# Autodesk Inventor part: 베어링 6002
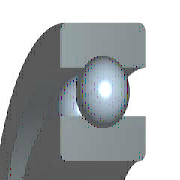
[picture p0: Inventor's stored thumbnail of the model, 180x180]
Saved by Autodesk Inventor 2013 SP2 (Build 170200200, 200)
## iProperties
IsCustomPart: 0
Created: 2012-02
Part Number: 베어링 6002
Material: 강철, 연강
Description: 깊은 그루브 볼 베어링
Document SubType Name: Modeling
Standard: KS B 2023
Designer: mduedu
Standards Organization: KS
Language: ko-KR
Size Designation: 6002 - 15 x 32 x 9
Categories: <MemberInstance><Categories><Category DisplayName="샤프트 부품" InternalName="7f7aeb1f-a693-4053-b835-cee3144e0d98" Mnemonic="SHFT"><Category DisplayName="베어링" Inter
Density: 1 g/cm^3
Author: mduedu
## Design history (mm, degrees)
sketch "스케치" dims "d0" = 4.42 (= -0.26 x WD + 0.26 x BD)
  geometry: L1 (2.29, 11.75)-(6.71, 11.75); L2 (4.5, 11.75)-(4.5, 9.54); L3 (4.5, 11.75)-(4.5, 13.96); L4 (2.858, 10.271)-(0, 10.271); L5 (0, 7.5)-(9, 7.5); L6 (2.858, 13.229)-(0, 13.229); L7 (0, 16)-(9, 16); L8 (9, 7.5)-(9, 10.271); L9 (6.142, 10.271)-(9, 10.271); L10 (6.142, 13.229)-(9, 13.229); L11 (9, 16)-(9, 13.229); L12 (-1.4, 0)-(8.4, 0) reference; L13 (0, -0.3)-(0, 5.3) reference
  constraints: 22 end point, 4 point on line, 2 collinear, 2 perpendicular, 2 symmetric about line, 1 midpoint, 1 parallel, 14 other
  dimensions: "d9" = 15 diameter of L5 L12 (= WD); "d11" = 32 diameter of L7 L12 (= BD); "d12" = 9 distance between parallel lines of L8 L13 (= KB); "d13" = 20.542 diameter of L9 L12 (= 0.326 x BD + 0.674 x WD)
revolve "본체" stored, may be unused: angle "d6" = 90 deg
revolve "볼" stored, may be unused: angle "d7" = 90 deg
pattern_circular "IDS_ARRAYBALL[SIMPL:T]" dims angle "d3" = 360 deg
body "Solid1"
fillet "모깎기1" dims "d1" = 0.3 (= KRS)
other parameters: "WD" = 15 [user parameter; used in 5 equation terms], "BD" = 32 [user parameter; used in 5 equation terms], "KB" = 9 [user parameter; used in 1 equation term], "KRS" = 0.3 [user parameter; used in 1 equation term], "d4" = 0, "d5" = 0, "d8" = 0, "d14" = 0, "d15" = 0, "BBA" = 0 [user parameter], "BC0" = 2850000 [user parameter], "BC" = 5590000 [user parameter], "BR" = 16 (= 0.5 x BD) [user parameter], "WR" = 7.5 (= 0.5 x WD) [user parameter]
